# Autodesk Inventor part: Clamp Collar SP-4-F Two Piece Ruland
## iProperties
Title: Clamp Collar SP-4-F Two Piece Ruland
Author: cdotson
Shininess: 50.0
PropertySet Name: _Private Model Information
Created: 2001-02
Part Number: SP-4-A
Material: Aluminum-6061
Document SubType Name: Modeling
Designer: cdotson
Control State: 0
Master: False
Checked Out: False
PropertySet Name: Design Tracking Control
Density: 2.71
Volumn: 1.016368479534301
Area: 9.524446528983542
PropertySet Name: Model Information
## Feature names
1. Extrusion2
2. Extrusion3
3. Hole1
4. Extrusion5
5. Fillet1
6. Mirror2
